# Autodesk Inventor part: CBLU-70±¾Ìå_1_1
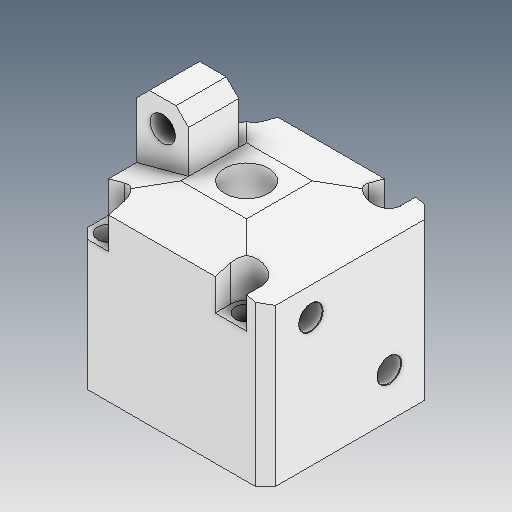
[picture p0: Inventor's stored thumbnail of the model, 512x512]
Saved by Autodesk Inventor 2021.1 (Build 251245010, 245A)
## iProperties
Created: 2021-05
Part Number: CBLU-70±¾Ìå_1_1
Material: Ogólny
Document SubType Name: Modeling
Designer: user
Density: 1 g/cm^3
Appearance: Domyślna
Author: user
Revision Number: ÈÎºÎ
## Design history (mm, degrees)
feature "ÊäÈë1"
feature "ÊäÈë2"
node "Bryła1"
node "Bryła2"
